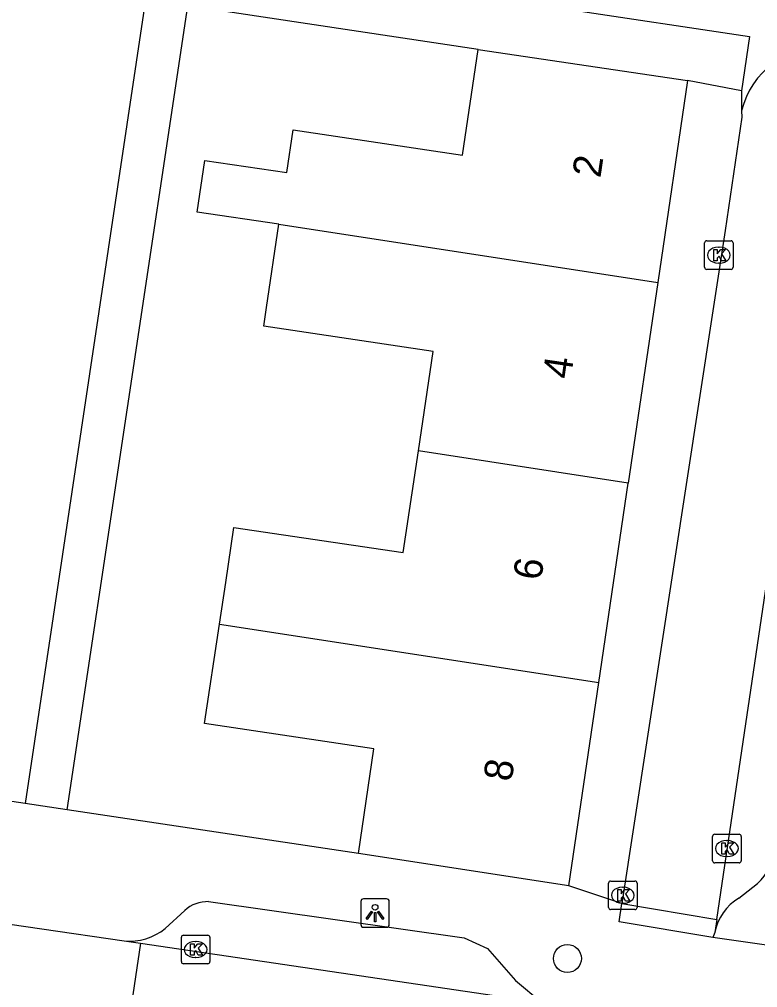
# Model space of a CAD drawing. Extents: x 163686 to 164493, y 382719 to 383870.
# Drawn here: x 164018.55 to 164044.41, y 383054.57 to 383088.49 of the extents above; entities that cross this region are included whole.
import ezdxf

# ---------------------------------------------------------------- set-up
doc = ezdxf.new("R2010")
doc.units = 0
for name, color, linetype in [('IMGEO_Boom', 7, 'Continuous'), ('IMGEO_Kolk', 7, 'Continuous'), ('IMGEO_Lichtpunt', 7, 'Continuous'), ('IMGEO_Pand', 7, 'Continuous'), ('IMGEO_Pand_nummerreeks', 7, 'Continuous'), ('IMGEO_Parkeervlak_open', 7, 'Continuous'), ('IMGEO_Rijbaan_lokaal_open', 7, 'Continuous'), ('IMGEO_Voetpad_open', 7, 'Continuous')]:
    doc.layers.add(name, color=color, linetype=linetype)

msp = doc.modelspace()

# ---------------------------------------------------------------- linework, layer by layer
at = {"layer": 'IMGEO_Boom'}
msp.add_circle((164037.749, 383055.594), 0.489, dxfattribs=at)
at = {"layer": 'IMGEO_Kolk'}
for p, q in [((164042.553, 383079.805), (164042.553, 383080.657)), ((164042.628, 383080.731), (164043.48, 383080.731)), ((164043.554, 383080.657), (164043.554, 383079.805)), ((164043.041, 383080.511), (164043.066, 383080.511)), ((164043.064, 383079.951), (164043.039, 383079.951)), ((164043.48, 383079.731), (164042.628, 383079.731)), ((164042.835, 383059.018), (164042.835, 383059.87)), ((164042.91, 383059.944), (164043.762, 383059.944)), ((164043.836, 383059.87), (164043.836, 383059.018)), ((164043.323, 383059.724), (164043.348, 383059.724)), ((164043.346, 383059.164), (164043.321, 383059.164)), ((164043.762, 383058.944), (164042.91, 383058.944)), ((164039.188, 383057.382), (164039.188, 383058.234)), ((164039.263, 383058.308), (164040.115, 383058.308)), ((164040.189, 383058.234), (164040.189, 383057.382)), ((164039.676, 383058.088), (164039.701, 383058.088)), ((164039.699, 383057.528), (164039.674, 383057.528)), ((164040.115, 383057.308), (164039.263, 383057.308)), ((164024.222, 383055.484), (164024.222, 383056.336)), ((164024.297, 383056.41), (164025.149, 383056.41)), ((164024.71, 383056.19), (164024.735, 383056.19)), ((164025.223, 383056.336), (164025.223, 383055.484)), ((164024.733, 383055.63), (164024.708, 383055.63)), ((164025.149, 383055.41), (164024.297, 383055.41))]:
    msp.add_line(p, q, dxfattribs=at)
for points in [[(164042.553, 383079.805), (164042.553, 383080.657)], [(164042.628, 383080.731), (164043.48, 383080.731)], [(164043.554, 383080.657), (164043.554, 383079.805)], [(164042.874, 383080.431), (164042.997, 383080.431), (164042.997, 383080.28), (164043.127, 383080.431), (164043.291, 383080.431), (164043.145, 383080.28), (164043.298, 383080.031), (164043.146, 383080.031), (164043.061, 383080.195), (164042.997, 383080.128), (164042.997, 383080.031), (164042.874, 383080.031), (164042.874, 383080.431)], [(164043.48, 383079.731), (164042.628, 383079.731)], [(164042.835, 383059.018), (164042.835, 383059.87)], [(164042.91, 383059.944), (164043.762, 383059.944)], [(164043.836, 383059.87), (164043.836, 383059.018)], [(164043.156, 383059.644), (164043.279, 383059.644), (164043.279, 383059.493), (164043.409, 383059.644), (164043.573, 383059.644), (164043.427, 383059.493), (164043.58, 383059.244), (164043.428, 383059.244), (164043.343, 383059.408), (164043.279, 383059.341), (164043.279, 383059.244), (164043.156, 383059.244), (164043.156, 383059.644)], [(164043.762, 383058.944), (164042.91, 383058.944)], [(164039.188, 383057.382), (164039.188, 383058.234)], [(164039.263, 383058.308), (164040.115, 383058.308)], [(164040.189, 383058.234), (164040.189, 383057.382)], [(164039.509, 383058.008), (164039.632, 383058.008), (164039.632, 383057.857), (164039.762, 383058.008), (164039.926, 383058.008), (164039.78, 383057.857), (164039.933, 383057.608), (164039.781, 383057.608), (164039.696, 383057.772), (164039.632, 383057.705), (164039.632, 383057.608), (164039.509, 383057.608), (164039.509, 383058.008)], [(164040.115, 383057.308), (164039.263, 383057.308)], [(164024.222, 383055.484), (164024.222, 383056.336)], [(164024.297, 383056.41), (164025.149, 383056.41)], [(164024.543, 383056.11), (164024.666, 383056.11), (164024.666, 383055.959), (164024.796, 383056.11), (164024.96, 383056.11), (164024.814, 383055.959), (164024.967, 383055.71), (164024.815, 383055.71), (164024.73, 383055.874), (164024.666, 383055.807), (164024.666, 383055.71), (164024.543, 383055.71), (164024.543, 383056.11)], [(164025.223, 383056.336), (164025.223, 383055.484)], [(164025.149, 383055.41), (164024.297, 383055.41)]]:
    msp.add_lwpolyline(points, dxfattribs=at)
for centre, start, end in [((164042.63, 383080.655), 91.552, 178.448), ((164042.63, 383080.655), 91.552, 178.448), ((164043.478, 383080.655), 1.552, 88.448), ((164043.478, 383080.655), 1.552, 88.448), ((164042.63, 383079.807), 181.552, 268.448), ((164042.63, 383079.807), 181.552, 268.448), ((164043.478, 383079.807), 271.552, 358.448), ((164043.478, 383079.807), 271.552, 358.448), ((164042.912, 383059.868), 91.552, 178.448), ((164042.912, 383059.868), 91.552, 178.448), ((164043.76, 383059.868), 1.552, 88.448), ((164043.76, 383059.868), 1.552, 88.448), ((164042.912, 383059.02), 181.552, 268.448), ((164042.912, 383059.02), 181.552, 268.448), ((164043.76, 383059.02), 271.552, 358.448), ((164043.76, 383059.02), 271.552, 358.448), ((164039.265, 383058.232), 91.552, 178.448), ((164039.265, 383058.232), 91.552, 178.448), ((164040.113, 383058.232), 1.552, 88.448), ((164040.113, 383058.232), 1.552, 88.448), ((164039.265, 383057.384), 181.552, 268.448), ((164039.265, 383057.384), 181.552, 268.448), ((164040.113, 383057.384), 271.552, 358.448), ((164040.113, 383057.384), 271.552, 358.448), ((164024.299, 383056.334), 91.552, 178.448), ((164024.299, 383056.334), 91.552, 178.448), ((164025.147, 383056.334), 1.552, 88.448), ((164025.147, 383056.334), 1.552, 88.448), ((164024.299, 383055.486), 181.552, 268.448), ((164024.299, 383055.486), 181.552, 268.448), ((164025.147, 383055.486), 271.552, 358.448), ((164025.147, 383055.486), 271.552, 358.448)]:
    msp.add_arc(centre, 0.0765, start, end, dxfattribs=at)
for centre, major_axis, ratio, start_param, end_param in [((164043.04, 383080.231), (-0.387, 0.002), 0.722429, 4.712389, 7.853982), ((164043.065, 383080.231), (-0.39, 0.002), 0.717154, 1.570796, 4.712389), ((164043.322, 383059.444), (-0.387, 0.002), 0.722429, 4.712389, 7.853982), ((164043.347, 383059.444), (-0.39, 0.002), 0.717154, 1.570796, 4.712389), ((164039.675, 383057.808), (-0.387, 0.002), 0.722429, 4.712389, 7.853982), ((164039.7, 383057.808), (-0.39, 0.002), 0.717154, 1.570796, 4.712389), ((164024.709, 383055.91), (-0.387, 0.002), 0.722429, 4.712389, 7.853982), ((164024.734, 383055.91), (-0.39, 0.002), 0.717154, 1.570796, 4.712389)]:
    msp.add_ellipse(centre, major_axis=major_axis, ratio=ratio, start_param=start_param, end_param=end_param, dxfattribs=at)
at = {"layer": 'IMGEO_Lichtpunt'}
for p, q in [((164030.51, 383057.59), (164030.51, 383056.783)), ((164030.51, 383057.59), (164030.51, 383056.783)), ((164031.412, 383057.685), (164030.604, 383057.685)), ((164031.412, 383057.685), (164030.604, 383057.685)), ((164031.506, 383056.783), (164031.506, 383057.59)), ((164031.506, 383056.783), (164031.506, 383057.59)), ((164030.604, 383056.689), (164031.412, 383056.689)), ((164030.604, 383056.689), (164031.412, 383056.689))]:
    msp.add_line(p, q, dxfattribs=at)
for points in [[(164030.884, 383057.254), (164030.923, 383057.226), (164030.735, 383056.964), (164030.697, 383056.991), (164030.884, 383057.254)], [(164030.986, 383057.206), (164031.033, 383057.206), (164031.033, 383056.884), (164030.986, 383056.884), (164030.986, 383057.206)], [(164031.096, 383057.226), (164031.134, 383057.253), (164031.321, 383056.991), (164031.282, 383056.963), (164031.096, 383057.226)]]:
    msp.add_lwpolyline(points, dxfattribs=at)
msp.add_circle((164031.009, 383057.388), 0.0994, dxfattribs=at)
for centre, start, end in [((164030.604, 383057.59), 90, 180), ((164030.604, 383057.59), 90, 180), ((164031.412, 383057.59), 0, 90), ((164031.412, 383057.59), 0, 90), ((164030.604, 383056.783), 180, 270), ((164030.604, 383056.783), 180, 270), ((164031.412, 383056.783), 270, 0), ((164031.412, 383056.783), 270, 360)]:
    msp.add_arc(centre, 0.0946, start, end, dxfattribs=at)
at = {"layer": 'IMGEO_Pand'}
for points in [[(164027.643, 383081.312), (164024.777, 383081.738), (164025.045, 383083.549), (164027.913, 383083.122), (164028.136, 383084.621), (164034.07, 383083.737), (164034.621, 383087.436)], [(164034.621, 383087.436), (164041.955, 383086.344)], [(164041.955, 383086.344), (164040.913, 383079.27)], [(164032.527, 383073.373), (164033.045, 383076.853), (164027.111, 383077.737), (164027.209, 383078.398), (164027.643, 383081.312)], [(164027.643, 383081.312), (164040.913, 383079.27)], [(164040.913, 383079.27), (164039.878, 383072.242)], [(164025.558, 383067.31), (164025.775, 383068.767), (164026.062, 383070.695), (164031.996, 383069.811), (164032.527, 383073.373)], [(164039.878, 383072.242), (164032.527, 383073.373)], [(164038.851, 383065.265), (164039.878, 383072.242)], [(164030.426, 383059.273), (164030.971, 383062.937), (164025.038, 383063.821), (164025.558, 383067.31)], [(164025.558, 383067.31), (164038.851, 383065.265)], [(164037.802, 383058.142), (164038.851, 383065.265)], [(164037.802, 383058.142), (164030.426, 383059.273)]]:
    msp.add_lwpolyline(points, dxfattribs=at)
at = {"layer": 'IMGEO_Parkeervlak_open'}
msp.add_lwpolyline([(164043.757, 383057.707), (164044.412, 383058.222)], dxfattribs=at)
for centre, radius, start, end in [((164042.941, 383059.772), 2.137, 313.5087, 349.9478), ((164044.665, 383056.169), 1.786, 120.5437, 169.0887)]:
    msp.add_arc(centre, radius, start, end, dxfattribs=at)
at = {"layer": 'IMGEO_Rijbaan_lokaal_open'}
for points in [[(164043.851, 383085.289), (164043.854, 383085.06), (164043.271, 383081.092), (164039.653, 383057.519)], [(164042.978, 383056.96), (164045.921, 383076.806), (164045.976, 383077.163)], [(164042.84, 383056.324), (164039.556, 383056.876), (164039.653, 383057.519)], [(164039.653, 383057.519), (164042.978, 383056.96)], [(164016.437, 383057.059), (164022.215, 383056.211)], [(164042.978, 383056.96), (164042.911, 383056.507)], [(164042.911, 383056.507), (164042.84, 383056.324)], [(164022.788, 383056.127), (164022.095, 383051.409)], [(164022.215, 383056.211), (164022.788, 383056.127)], [(164022.788, 383056.127), (164036.851, 383054.058)]]:
    msp.add_lwpolyline(points, dxfattribs=at)
msp.add_arc((164046.687, 383084.602), 2.919, 86.5909, 166.3776, dxfattribs=at)
at = {"layer": 'IMGEO_Voetpad_open'}
for points in [[(164031.356, 383089.811), (164044.132, 383087.893), (164043.843, 383085.984)], [(164022.964, 383089.182), (164018.747, 383061.027)], [(164020.223, 383060.805), (164024.449, 383088.96)], [(164034.621, 383087.436), (164024.449, 383088.96)], [(164043.843, 383085.984), (164041.955, 383086.344)], [(164043.843, 383085.984), (164043.851, 383085.289)], [(164018.747, 383061.027), (164008.789, 383062.521)], [(164020.223, 383060.805), (164018.747, 383061.027)], [(164030.426, 383059.273), (164020.223, 383060.805)], [(164039.653, 383057.519), (164037.802, 383058.142)], [(164025.178, 383057.585), (164034.127, 383056.318), (164034.947, 383055.94), (164035.934, 383054.824), (164036.851, 383054.058)], [(164023.656, 383056.646), (164024.342, 383057.275)], [(164051.188, 383055.135), (164042.84, 383056.324)]]:
    msp.add_lwpolyline(points, dxfattribs=at)
for centre, radius, start, end in [((164025.134, 383056.421), 1.165, 87.8374, 132.8535), ((164022.405, 383058.186), 1.984, 264.5086, 309.0867)]:
    msp.add_arc(centre, radius, start, end, dxfattribs=at)

# ---------------------------------------------------------------- texts
at = {"layer": 'IMGEO_Pand_nummerreeks'}
for s, rotation, p in [('2', 81.6236, (164038.902, 383082.911)), ('4', 81.6236, (164037.864, 383075.863)), ('6', 81.6229, (164036.826, 383068.812)), ('8', 81.6229, (164035.789, 383061.766))]:
    msp.add_text(s, height=1, rotation=rotation, dxfattribs=at).set_placement(p)

doc.saveas('drawing.dxf')
